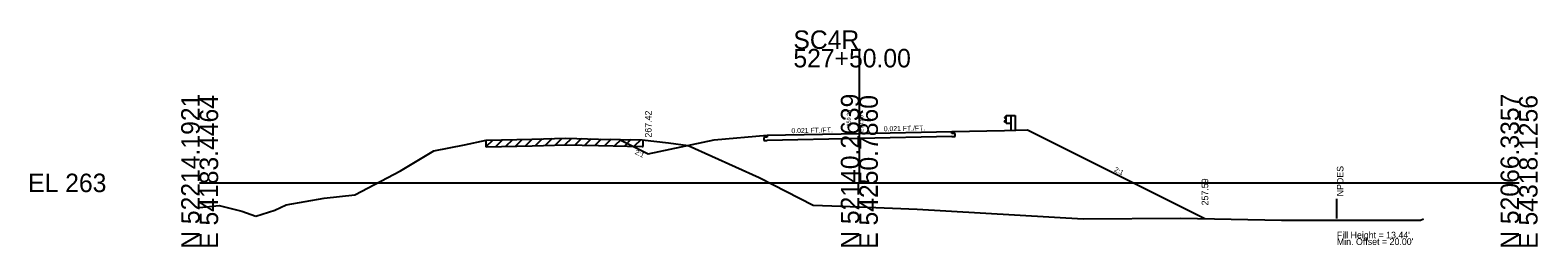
# Model space of a CAD drawing. Extents: x 7498 to 13027, y 90095 to 109625.
# Drawn here: x 9498.3 to 9726.8, y 97595.5 to 97628.3 of the extents above; entities that cross this region are included whole.
import ezdxf

# ---------------------------------------------------------------- set-up
doc = ezdxf.new("R2010")
doc.units = 0
for name, color, linetype in [('Level 10', 7, 'Continuous'), ('Level 11', 7, 'Continuous'), ('Level 12', 7, 'Continuous'), ('Level 24', 7, 'Continuous'), ('Level 32', 7, 'Continuous'), ('Level 33', 7, 'Continuous'), ('Level 50', 7, 'Continuous'), ('Level 55', 7, 'Continuous'), ('Level 59', 7, 'Continuous'), ('Level 6', 7, 'Continuous'), ('Level 60', 7, 'Continuous'), ('Level 61', 7, 'Continuous'), ('Level 63', 7, 'Continuous'), ('Level 7', 7, 'Continuous')]:
    doc.layers.add(name, color=color, linetype=linetype)

msp = doc.modelspace()

# ---------------------------------------------------------------- linework, layer by layer
at = {"layer": 'Level 11'}
for p, q in [((9609.99, 97612.07), (9609.49, 97612.05)), ((9609.49, 97612.05), (9609.49, 97611.57)), ((9609.99, 97612.37), (9609.99, 97612.07)), ((9637.99, 97612.65), (9637.99, 97612.95)), ((9638.49, 97612.66), (9637.99, 97612.65)), ((9637.99, 97612.17), (9638.49, 97612.18)), ((9638.49, 97612.18), (9638.49, 97612.66)), ((9609.49, 97611.57), (9609.99, 97611.59))]:
    msp.add_line(p, q, dxfattribs=at)
at = {"layer": 'Level 12'}
for p, q in [((9623.99, 97611.88), (9609.99, 97611.59)), ((9637.99, 97612.17), (9623.99, 97611.88))]:
    msp.add_line(p, q, dxfattribs=at)
at = {"layer": 'Level 24'}
for p, q in [((9646.26, 97615.29), (9645.99, 97615.09)), ((9645.99, 97615.09), (9645.99, 97615.04)), ((9645.99, 97615.04), (9646.26, 97614.84)), ((9645.99, 97614.52), (9646.26, 97614.72)), ((9645.99, 97614.47), (9645.99, 97614.52)), ((9646.26, 97614.27), (9645.99, 97614.47)), ((9646.26, 97614.2), (9646.26, 97615.36)), ((9646.26, 97615.36), (9646.93, 97615.36)), ((9646.26, 97614.2), (9646.93, 97614.2)), ((9646.93, 97615.36), (9646.93, 97613.13)), ((9646.93, 97615.36), (9647.6, 97615.36)), ((9647.6, 97615.36), (9647.6, 97613.15))]:
    msp.add_line(p, q, dxfattribs=at)
at = {"layer": 'Level 55'}
msp.add_line((9696.37, 97599.75), (9696.37, 97602.75), dxfattribs=at)
at = {"layer": 'Level 59'}
for p, q in [((9609.99, 97612.37), (9623.99, 97612.66)), ((9623.99, 97612.66), (9637.99, 97612.95))]:
    msp.add_line(p, q, dxfattribs=at)
at = {"layer": 'Level 6'}
for p, q in [((9601.99, 97611.7), (9609.99, 97612.37)), ((9637.99, 97612.95), (9645.99, 97613.11)), ((9645.99, 97613.11), (9649.49, 97613.19))]:
    msp.add_line(p, q, dxfattribs=at)
at = {"layer": 'Level 60'}
for p, q in [((9574.37, 97611.78), (9579.49, 97611.93)), ((9579.49, 97611.93), (9584.45, 97611.81)), ((9554.46, 97606.97), (9559.51, 97610)), ((9559.51, 97610), (9564.15, 97610.91)), ((9564.15, 97610.91), (9567.43, 97611.63)), ((9567.43, 97611.63), (9574.37, 97611.78)), ((9584.45, 97611.81), (9591.07, 97611.7)), ((9591.07, 97611.7), (9595.05, 97611.25)), ((9595.05, 97611.25), (9598.02, 97610.82)), ((9598.02, 97610.82), (9608.82, 97605.98)), ((9547.51, 97603.33), (9554.46, 97606.97)), ((9608.82, 97605.98), (9617.01, 97601.8)), ((9537.09, 97601.84), (9542.89, 97602.82)), ((9542.89, 97602.82), (9547.51, 97603.33)), ((9523.99, 97601.42), (9526.93, 97601.75)), ((9526.93, 97601.75), (9530.41, 97600.88)), ((9530.41, 97600.88), (9532.51, 97600.13)), ((9532.51, 97600.13), (9535.41, 97601)), ((9535.41, 97601), (9537.09, 97601.84)), ((9617.01, 97601.8), (9623.99, 97601.52)), ((9623.99, 97601.52), (9632.75, 97601.17)), ((9632.75, 97601.17), (9657.92, 97599.73)), ((9657.92, 97599.73), (9672.7, 97599.81)), ((9672.7, 97599.81), (9687.97, 97599.53)), ((9687.97, 97599.53), (9696.75, 97599.53)), ((9696.75, 97599.53), (9709.07, 97599.53)), ((9709.07, 97599.53), (9709.51, 97599.73))]:
    msp.add_line(p, q, dxfattribs=at)
at = {"layer": 'Level 61'}
for p, q in [((9578.9, 97611.91), (9577.87, 97610.88)), ((9580.36, 97611.91), (9579.37, 97610.93)), ((9568.41, 97611.65), (9567.37, 97610.61)), ((9567.37, 97611.61), (9567.37, 97610.61)), ((9567.37, 97610.61), (9567.43, 97610.63)), ((9567.43, 97610.63), (9574.37, 97610.78)), ((9569.9, 97611.68), (9568.87, 97610.66)), ((9571.4, 97611.71), (9570.37, 97610.69)), ((9572.9, 97611.75), (9571.87, 97610.73)), ((9574.4, 97611.78), (9573.37, 97610.76)), ((9574.37, 97610.78), (9579.49, 97610.93)), ((9575.9, 97611.83), (9574.87, 97610.8)), ((9577.4, 97611.87), (9576.37, 97610.84)), ((9579.49, 97610.93), (9584.45, 97610.81)), ((9581.85, 97611.87), (9580.87, 97610.9)), ((9583.35, 97611.84), (9582.37, 97610.86)), ((9584.85, 97611.8), (9583.87, 97610.82)), ((9584.45, 97610.81), (9591.07, 97610.7)), ((9586.36, 97611.78), (9585.37, 97610.8)), ((9587.86, 97611.75), (9586.87, 97610.77)), ((9589.36, 97611.73), (9588.37, 97610.75)), ((9590.86, 97611.7), (9589.87, 97610.72)), ((9591.07, 97610.7), (9591.22, 97610.68)), ((9591.22, 97610.68), (9591.22, 97611.68))]:
    msp.add_line(p, q, dxfattribs=at)
at = {"layer": 'Level 63'}
for p, q in [((9623.99, 97605.16), (9623.99, 97625.47)), ((9523.99, 97605.16), (9623.99, 97605.16)), ((9623.99, 97605.16), (9723.99, 97605.16))]:
    msp.add_line(p, q, dxfattribs=at)
at = {"layer": 'Level 7'}
for p, q in [((9649.49, 97613.19), (9676.37, 97599.75)), ((9587.62, 97611.76), (9591.99, 97609.57)), ((9591.99, 97609.57), (9601.99, 97611.7))]:
    msp.add_line(p, q, dxfattribs=at)

# ---------------------------------------------------------------- texts
at = {"layer": 'Level 10'}
msp.add_text('259.36', height=0.6, rotation=90, dxfattribs=at).set_placement((9622.69, 97613.71))
at = {"layer": 'Level 32'}
for s, rotation, p in [('0.021 FT./FT.', 1.1916, (9613.7, 97612.69)), ('0.021 FT./FT.', 1.1916, (9627.7, 97612.98)), ('2:1', 333.435, (9589.89, 97609.58)), ('2:1', 333.435, (9662.54, 97606.94))]:
    msp.add_text(s, height=0.75, rotation=rotation, dxfattribs=at).set_placement(p)
at = {"layer": 'Level 33'}
for s, p in [('267.42', (9592.49, 97612.03)), ('257.59', (9676.87, 97601.75))]:
    msp.add_text(s, height=1, rotation=90, dxfattribs=at).set_placement(p)
at = {"layer": 'Level 50'}
msp.add_text(' NPDES', height=1, rotation=90, dxfattribs=at).set_placement((9697.37, 97602.75))
for s, p in [("Fill Height = 13.44' ", (9696.37, 97596.75)), ("Min. Offset = 20.00' ", (9696.37, 97595.75))]:
    msp.add_text(s, height=1, dxfattribs=at).set_placement(p)
at = {"layer": 'Level 59'}
msp.add_text(' 270.50', height=0.6, rotation=90, dxfattribs=at).set_placement((9624.59, 97612.66))
at = {"layer": 'Level 63'}
for s, p in [('SC4R', (9613.99, 97625.47)), ('527+50.00', (9613.99, 97622.67)), ('EL 263', (9497.99, 97603.76))]:
    msp.add_text(s, height=2.8, dxfattribs=at).set_placement(p)
for s, p in [('N 52214.1921', (9523.99, 97595.16)), ('E 54183.4464', (9526.79, 97595.16)), ('N 52140.2639', (9623.99, 97595.16)), ('E 54250.7860', (9626.79, 97595.16)), ('N 52066.3357', (9723.99, 97595.16)), ('E 54318.1256', (9726.79, 97595.16))]:
    msp.add_text(s, height=2.8, rotation=90, dxfattribs=at).set_placement(p)

doc.saveas('drawing.dxf')
